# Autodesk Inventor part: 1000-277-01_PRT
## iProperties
Created: 2007-03
Part Number: 1000-277-01_PRT
Document SubType Name: Modeling
Designer: Andy Moles
Material: Steel
Author: Andy Moles
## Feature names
1. Base1
